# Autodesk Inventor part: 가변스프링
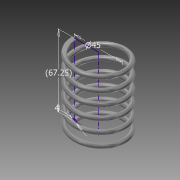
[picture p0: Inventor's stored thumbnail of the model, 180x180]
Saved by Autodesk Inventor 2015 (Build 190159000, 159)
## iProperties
Created: 2016-02
Part Number: 가변스프링
Material: 스테인레스 스틸
Document SubType Name: Modeling
Designer: Administrator
Density: 8 g/cm^3
Appearance: 반연마
Mass: 84.2127 g
Surface Area: 106.464 cm^2
Volume: 10.5266 cm^3
Author: Administrator
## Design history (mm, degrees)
sketch "스케치1"
  geometry: L1 (0, 0)-(22.5, 0); L2 (22.5, 0)-(22.5, 67.25); L3 (22.5, 67.25)-(0, 67.25); L4 (0, 67.25)-(0, 0); C1 r 2 at (22.5, 0)
  constraints: 8 end point, 2 parallel, 1 centre point, 1 coincident, 1 horizontal, 1 perpendicular
  dimensions: "d0" = 45 diameter of L2 L4; "d1" = 67.25 distance between parallel lines of L1 L3 (derived); "d2" = 4 diameter of C1
feature "코일1" sketch "스케치1" pitch "d3" = 10; turns "d5" = 6; dims "d4" = 67.25 (= d1), "d6" = 0, angle "d7" = 90 deg, angle "d8" = 90 deg, "d9" = 0, "d10" = 0
sketch "스케치2"
  geometry: L1 (-20.5, 0)-(-24.5, 0) reference; L2 (-20.5, 0)-(-24.5, 0) reference; 1 further point
  constraints: 2 horizontal alignment
extrude "돌출1" cut sketch "스케치2" stored distance "d11" = 10; taper "d12" = 0 deg
node "작업 평면1"
sketch "스케치3"
  geometry: L1 (-2, 0)-(2, 0) reference; 1 further point
  constraints: 1 horizontal alignment
extrude "돌출2" cut sketch "스케치3" stored distance "d13" = 10; taper "d14" = 0 deg
node "솔리드1"
node "절단 모서리 투영1"
node "절단 모서리 투영2"
node "절단 모서리 투영3"
